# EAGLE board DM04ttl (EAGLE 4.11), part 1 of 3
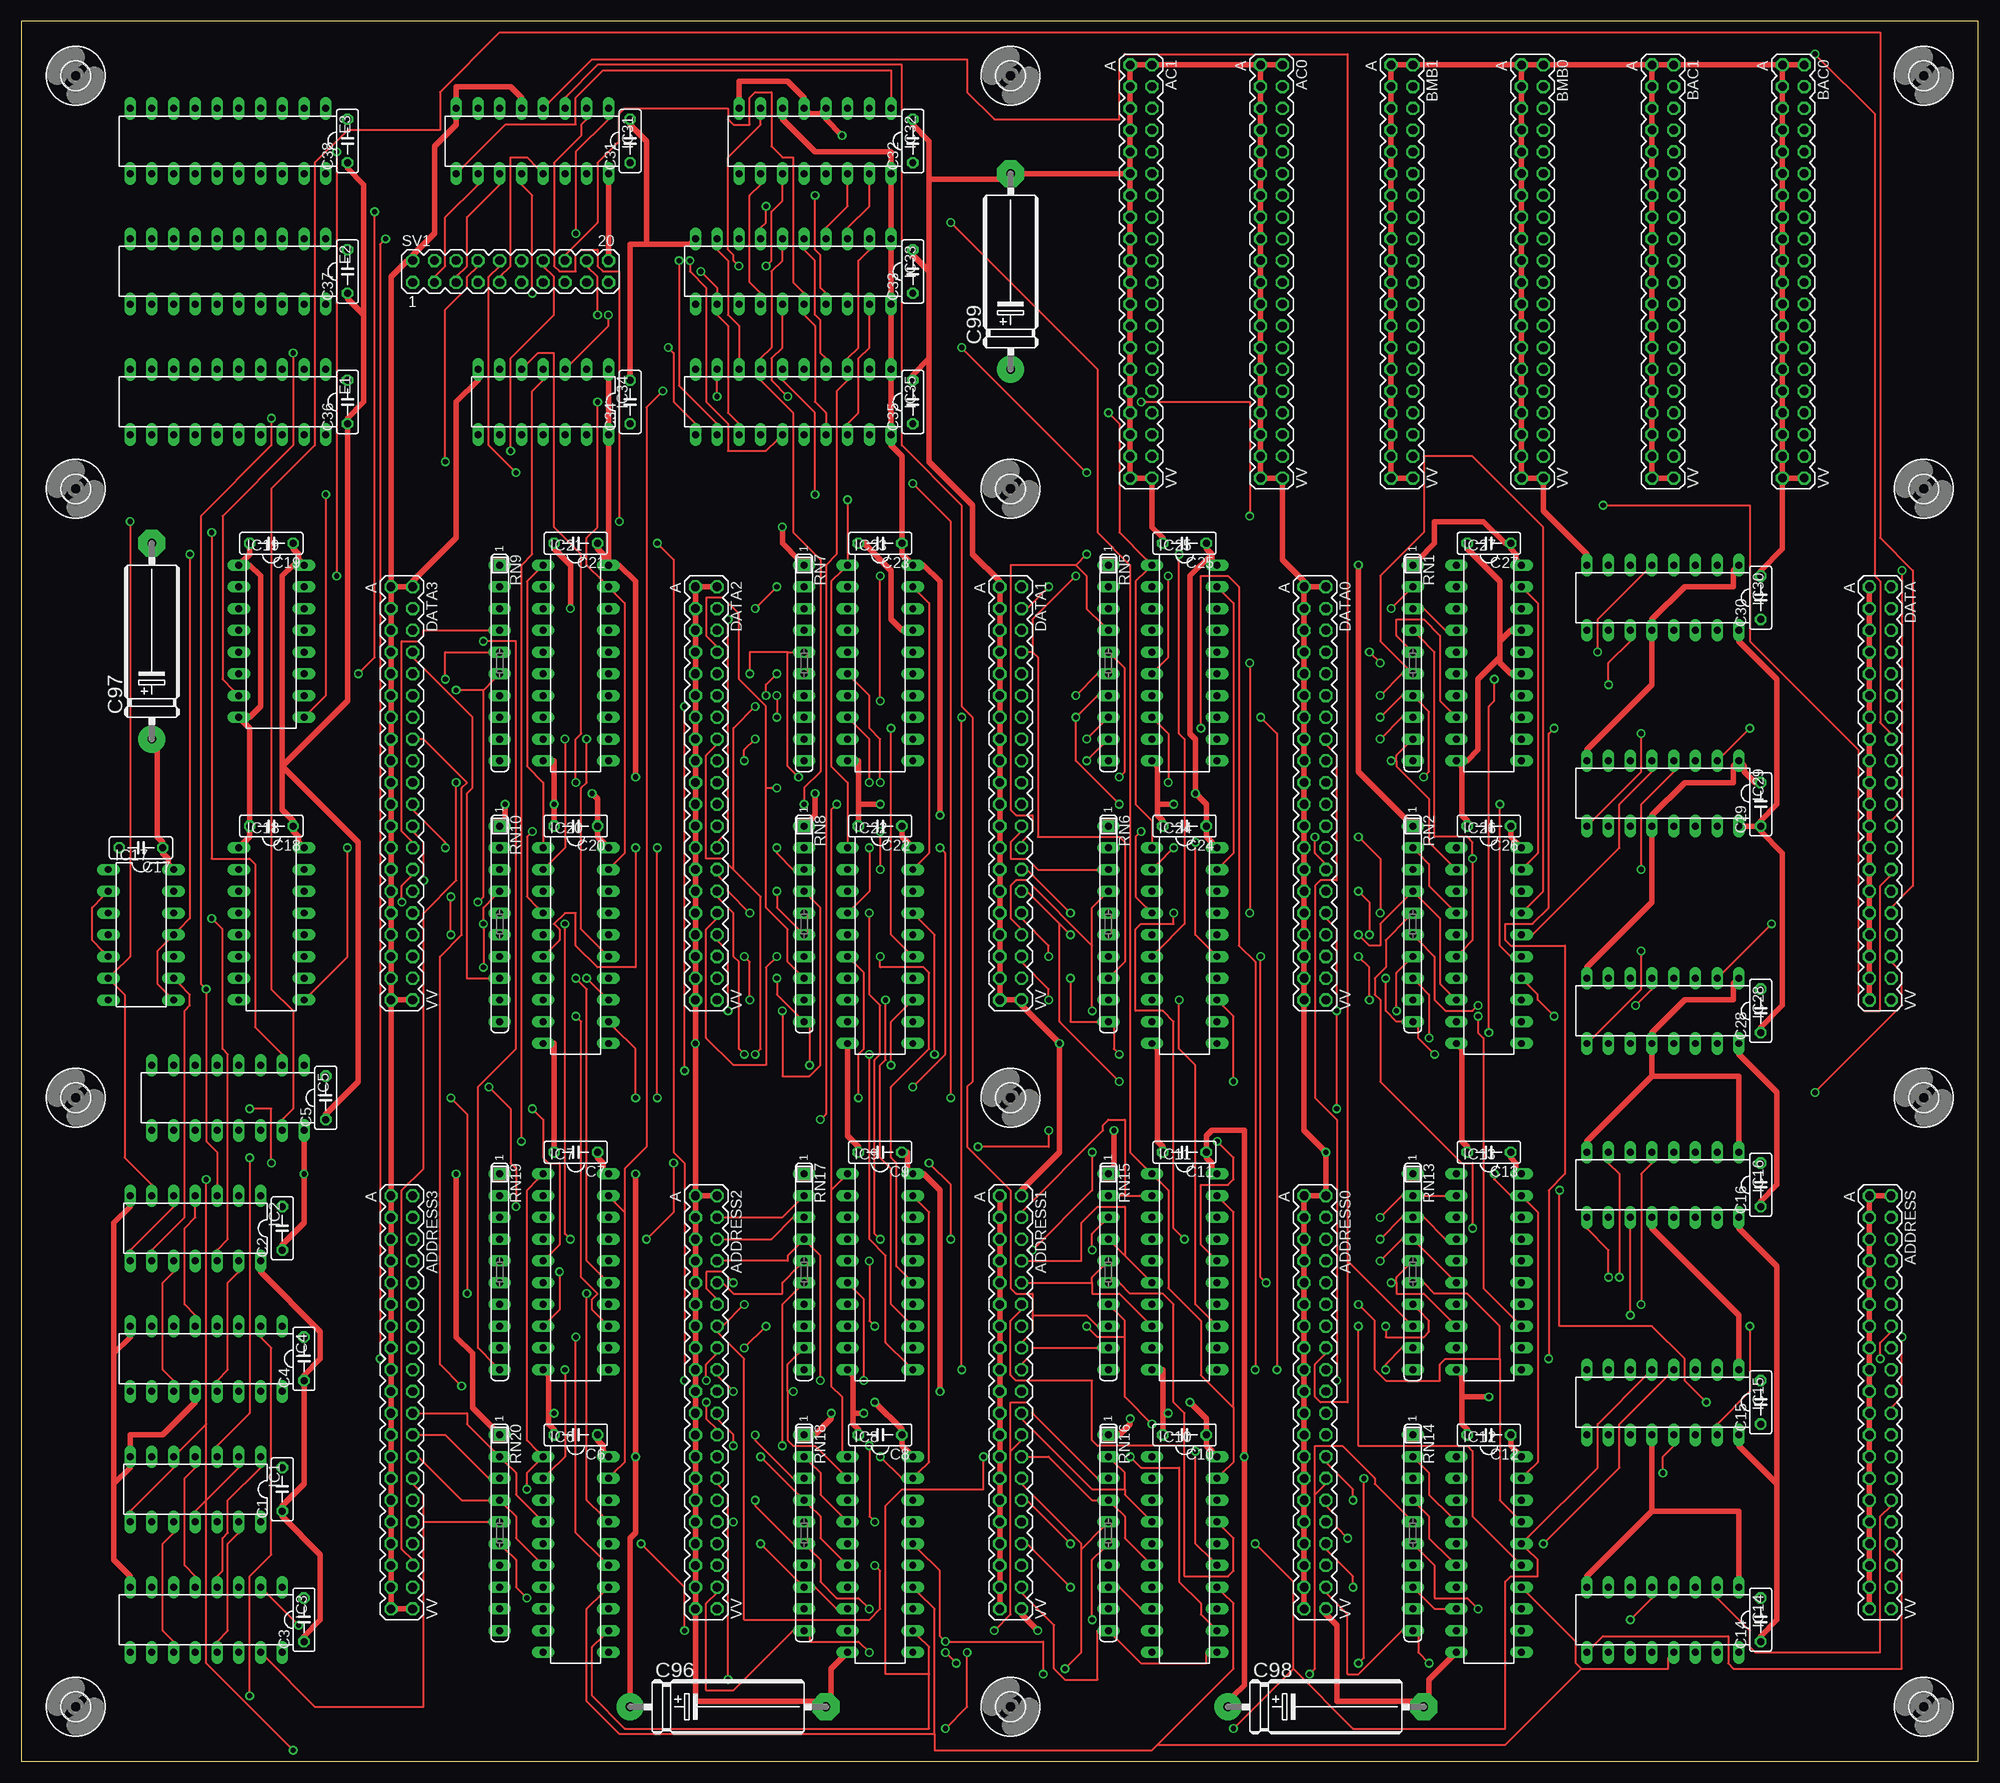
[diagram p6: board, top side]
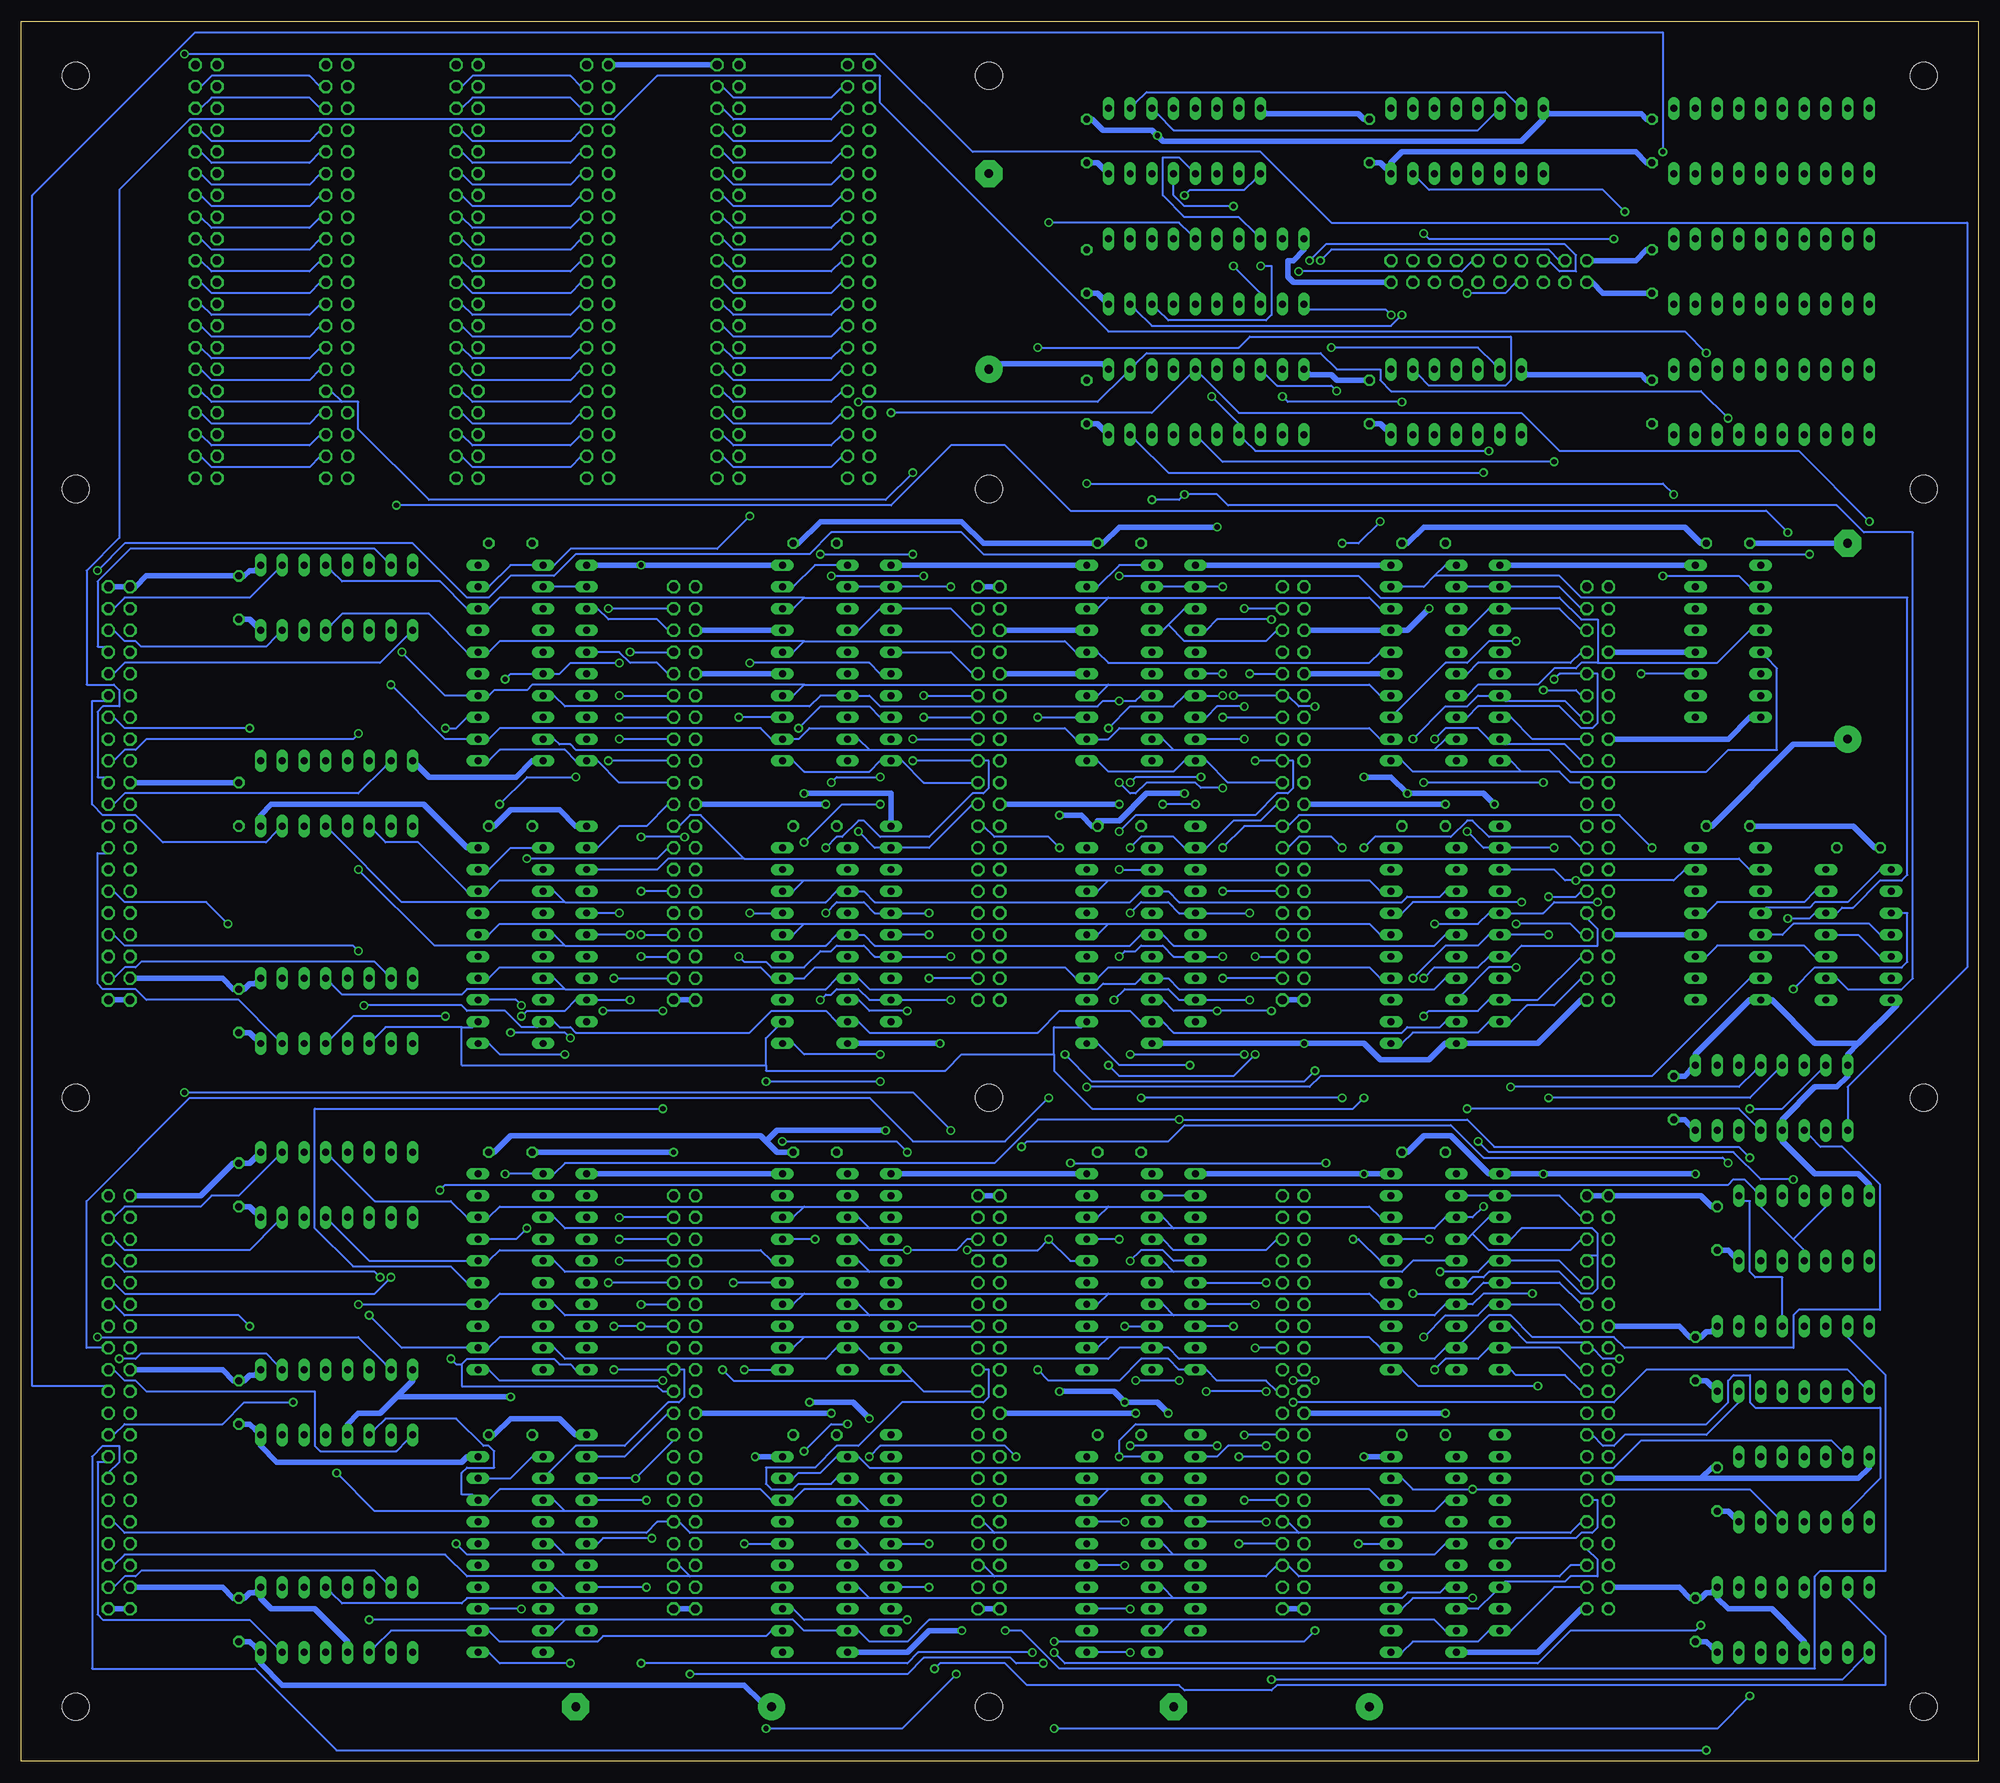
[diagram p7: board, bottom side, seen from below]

Size 228.6 x 203.2 mm. Coordinates in mm from the lower left corner, seen from the top.
Outline: 0,0 228.6,0 228.6,203.2 0,203.2 0,0
Copper layers (1*16): Top 0.035mm / dielectric 1.5mm / Bottom 0.035mm
Design rules "10mils": minimum track width 10mil, minimum drill 24mil, track to track 10mil, track to pad 10mil, pad to pad 10mil, via to via 10mil, smd to smd 10mil, copper to edge 25mil, drill to drill 10mil, minimum pad ring 10mil, minimum via ring 8mil, stop-mask expansion 0mil, vias tented up to drill 0mil, thermal gap 10mil
Net classes: 1 Supply: width 0.635 mm, drill 0.381 mm

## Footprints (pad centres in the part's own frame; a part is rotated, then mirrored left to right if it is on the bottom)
DEC40PINV = drill 1.016 octagon: A -24.13,-1.27; AA 3.81,-1.27; B -24.13,1.27; BB 3.81,1.27; C -21.59,-1.27; CC 6.35,-1.27; D -21.59,1.27; DD 6.35,1.27; E -19.05,-1.27; EE 8.89,-1.27; F -19.05,1.27; FF 8.89,1.27; H -16.51,-1.27; HH 11.43,-1.27; J -16.51,1.27; JJ 11.43,1.27; K -13.97,-1.27; KK 13.97,-1.27; L -13.97,1.27; LL 13.97,1.27; M -11.43,-1.27; MM 16.51,-1.27; N -11.43,1.27; NN 16.51,1.27; P -8.89,-1.27; PP 19.05,-1.27; R -8.89,1.27; RR 19.05,1.27; S -6.35,-1.27; SS 21.59,-1.27; T -6.35,1.27; TT 21.59,1.27; U -3.81,-1.27; UU 24.13,-1.27; V -3.81,1.27; VV 24.13,1.27; W -1.27,-1.27; X -1.27,1.27; Y 1.27,-1.27; Z 1.27,1.27
C050-025X075 = drill 0.813 octagon: 1 -2.54,0; 2 2.54,0
E22-6 = drill 1.016 pad 3.15 round: + -11.43,0 | drill 1.016 pad 3.15 octagon: - 11.43,0
DIL20 = drill 0.813 long: 1 -11.43,-3.81; 2 -8.89,-3.81; 3 -6.35,-3.81; 4 -3.81,-3.81; 5 -1.27,-3.81; 6 1.27,-3.81; 7 3.81,-3.81; 8 6.35,-3.81; 9 8.89,-3.81; 10 11.43,-3.81; 11 11.43,3.81; 12 8.89,3.81; 13 6.35,3.81; 14 3.81,3.81; 15 1.27,3.81; 16 -1.27,3.81; 17 -3.81,3.81; 18 -6.35,3.81; 19 -8.89,3.81; 20 -11.43,3.81
DIL14 = drill 0.813 long: 1 -7.62,-3.81; 2 -5.08,-3.81; 3 -2.54,-3.81; 4 0,-3.81; 5 2.54,-3.81; 6 5.08,-3.81; 7 7.62,-3.81; 8 7.62,3.81; 9 5.08,3.81; 10 2.54,3.81; 11 0,3.81; 12 -2.54,3.81; 13 -5.08,3.81; 14 -7.62,3.81
DIL16 = drill 0.813 long: 1 -8.89,-3.81; 2 -6.35,-3.81; 3 -3.81,-3.81; 4 -1.27,-3.81; 5 1.27,-3.81; 6 3.81,-3.81; 7 6.35,-3.81; 8 8.89,-3.81; 9 8.89,3.81; 10 6.35,3.81; 11 3.81,3.81; 12 1.27,3.81; 13 -1.27,3.81; 14 -3.81,3.81; 15 -6.35,3.81; 16 -8.89,3.81
SIL10 = drill 0.813 long: 1 -11.43,0; 2 -8.89,0; 3 -6.35,0; 4 -3.81,0; 5 -1.27,0; 6 1.27,0; 7 3.81,0; 8 6.35,0; 9 8.89,0; 10 11.43,0
MA10-2 = drill 1.016 octagon: 1 -11.43,-1.27; 2 -11.43,1.27; 3 -8.89,-1.27; 4 -8.89,1.27; 5 -6.35,-1.27; 6 -6.35,1.27; 7 -3.81,-1.27; 8 -3.81,1.27; 9 -1.27,-1.27; 10 -1.27,1.27; 11 1.27,-1.27; 12 1.27,1.27; 13 3.81,-1.27; 14 3.81,1.27; 15 6.35,-1.27; 16 6.35,1.27; 17 8.89,-1.27; 18 8.89,1.27; 19 11.43,-1.27; 20 11.43,1.27
3,2 = hole 3.2: 0,0

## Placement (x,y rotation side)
AC0  BC08J  [DEC40PINV]  146.05,173.99 270 top
AC1  BC08J  [DEC40PINV]  130.81,173.99 270 top
ADDRESS  BC08J  [DEC40PINV]  217.17,41.91 270 top
ADDRESS0  BC08J  [DEC40PINV]  151.13,41.91 270 top
ADDRESS1  BC08J  [DEC40PINV]  115.57,41.91 270 top
ADDRESS2  BC08J  [DEC40PINV]  80.01,41.91 270 top
ADDRESS3  BC08J  [DEC40PINV]  44.45,41.91 270 top
BAC0  BC08J  [DEC40PINV]  207.01,173.99 270 top
BAC1  BC08J  [DEC40PINV]  191.77,173.99 270 top
BMB0  BC08J  [DEC40PINV]  176.53,173.99 270 top
BMB1  BC08J  [DEC40PINV]  161.29,173.99 270 top
C1  .1uf  [C050-025X075]  30.48,31.75 90 top
C2  .1uf  [C050-025X075]  30.48,62.23 90 top
C3  .1uf  [C050-025X075]  33.02,16.51 90 top
C4  .1uf  [C050-025X075]  33.02,46.99 90 top
C5  .1uf  [C050-025X075]  35.56,77.47 90 top
C6  .1uf  [C050-025X075]  64.77,38.1 180 top
C7  .1uf  [C050-025X075]  64.77,71.12 180 top
C8  .1uf  [C050-025X075]  100.33,38.1 180 top
C9  .1uf  [C050-025X075]  100.33,71.12 180 top
C10  .1uf  [C050-025X075]  135.89,38.1 180 top
C11  .1uf  [C050-025X075]  135.89,71.12 180 top
C12  .1uf  [C050-025X075]  171.45,38.1 180 top
C13  .1uf  [C050-025X075]  171.45,71.12 180 top
C14  .1uf  [C050-025X075]  203.2,16.51 90 top
C15  .1uf  [C050-025X075]  203.2,41.91 90 top
C16  .1uf  [C050-025X075]  203.2,67.31 90 top
C17  .1uf  [C050-025X075]  13.97,106.68 180 top
C18  .1uf  [C050-025X075]  29.21,109.22 180 top
C19  .1uf  [C050-025X075]  29.21,142.24 180 top
C20  .1uf  [C050-025X075]  64.77,109.22 180 top
C21  .1uf  [C050-025X075]  64.77,142.24 180 top
C22  .1uf  [C050-025X075]  100.33,109.22 180 top
C23  .1uf  [C050-025X075]  100.33,142.24 180 top
C24  .1uf  [C050-025X075]  135.89,109.22 180 top
C25  .1uf  [C050-025X075]  135.89,142.24 180 top
C26  .1uf  [C050-025X075]  171.45,109.22 180 top
C27  .1uf  [C050-025X075]  171.45,142.24 180 top
C28  .1uf  [C050-025X075]  203.2,87.63 90 top
C29  .1uf  [C050-025X075]  203.2,111.76 90 top
C30  .1uf  [C050-025X075]  203.2,135.89 90 top
C31  .1uf  [C050-025X075]  71.12,189.23 90 top
C32  .1uf  [C050-025X075]  104.14,189.23 90 top
C33  .1uf  [C050-025X075]  104.14,173.99 90 top
C34  .1uf  [C050-025X075]  71.12,158.75 90 top
C35  .1uf  [C050-025X075]  104.14,158.75 90 top
C36  .1uf  [C050-025X075]  38.1,158.75 90 top
C37  .1uf  [C050-025X075]  38.1,173.99 90 top
C38  .1uf  [C050-025X075]  38.1,189.23 90 top
C96  100uf  [E22-6]  82.55,6.35 0 top
C97  100uf  [E22-6]  15.24,130.81 90 top
C98  100uf  [E22-6]  152.4,6.35 0 top
C99  100uf  [E22-6]  115.57,173.99 90 top
DATA  BC08J  [DEC40PINV]  217.17,113.03 270 top
DATA0  BC08J  [DEC40PINV]  151.13,113.03 270 top
DATA1  BC08J  [DEC40PINV]  115.57,113.03 270 top
DATA2  BC08J  [DEC40PINV]  80.01,113.03 270 top
DATA3  BC08J  [DEC40PINV]  44.45,113.03 270 top
E1  [DIL20]  24.13,158.75 180 top
E2  [DIL20]  24.13,173.99 180 top
E3  [DIL20]  24.13,189.23 180 top
IC1  74S02N  [DIL14]  20.32,31.75 180 top
IC2  74S02N  [DIL14]  20.32,62.23 180 top
IC3  AM26S10  [DIL16]  21.59,16.51 180 top
IC4  AM26S10  [DIL16]  21.59,46.99 180 top
IC5  AM26S10  [DIL16]  24.13,77.47 180 top
IC6  74S240N  [DIL20]  64.77,24.13 270 top
IC7  74S240N  [DIL20]  64.77,57.15 270 top
IC8  74S240N  [DIL20]  100.33,24.13 270 top
IC9  74S240N  [DIL20]  100.33,57.15 270 top
IC10  74S240N  [DIL20]  135.89,24.13 270 top
IC11  74S240N  [DIL20]  135.89,57.15 270 top
IC12  74S240N  [DIL20]  171.45,24.13 270 top
IC13  74S240N  [DIL20]  171.45,57.15 270 top
IC14  AM26S10  [DIL16]  191.77,16.51 180 top
IC15  AM26S10  [DIL16]  191.77,41.91 180 top
IC16  AM26S10  [DIL16]  191.77,67.31 180 top
IC17  74S02N  [DIL14]  13.97,96.52 270 top
IC18  AM26S10  [DIL16]  29.21,97.79 270 top
IC19  AM26S10  [DIL16]  29.21,130.81 270 top
IC20  74S240N  [DIL20]  64.77,95.25 270 top
IC21  74S240N  [DIL20]  64.77,128.27 270 top
IC22  74S240N  [DIL20]  100.33,95.25 270 top
IC23  74S240N  [DIL20]  100.33,128.27 270 top
IC24  74S240N  [DIL20]  135.89,95.25 270 top
IC25  74S240N  [DIL20]  135.89,128.27 270 top
IC26  74S240N  [DIL20]  171.45,95.25 270 top
IC27  74S240N  [DIL20]  171.45,128.27 270 top
IC28  AM26S10  [DIL16]  191.77,87.63 180 top
IC29  AM26S10  [DIL16]  191.77,113.03 180 top
IC30  AM26S10  [DIL16]  191.77,135.89 180 top
IC31  74LS148N  [DIL16]  59.69,189.23 180 top
IC32  74S138N  [DIL16]  92.71,189.23 180 top
IC33  74LS273N  [DIL20]  90.17,173.99 180 top
IC34  74S86N  [DIL14]  60.96,158.75 180 top
IC35  74LS273N  [DIL20]  90.17,158.75 180 top
RN1  [SIL10]  162.56,128.27 270 top
RN2  [SIL10]  162.56,97.79 270 top
RN5  [SIL10]  127,128.27 270 top
RN6  [SIL10]  127,97.79 270 top
RN7  [SIL10]  91.44,128.27 270 top
RN8  [SIL10]  91.44,97.79 270 top
RN9  [SIL10]  55.88,128.27 270 top
RN10  [SIL10]  55.88,97.79 270 top
RN13  [SIL10]  162.56,57.15 270 top
RN14  [SIL10]  162.56,26.67 270 top
RN15  [SIL10]  127,57.15 270 top
RN16  [SIL10]  127,26.67 270 top
RN17  [SIL10]  91.44,57.15 270 top
RN18  [SIL10]  91.44,26.67 270 top
RN19  [SIL10]  55.88,57.15 270 top
RN20  [SIL10]  55.88,26.67 270 top
SV1  [MA10-2]  57.15,173.99 0 top
U$1  [3,2]  222.25,6.35 270 top
U$2  [3,2]  6.35,196.85 270 top
U$3  [3,2]  222.25,196.85 270 top
U$4  [3,2]  6.35,6.35 270 top
U$5  [3,2]  115.57,196.85 270 top
U$6  [3,2]  115.57,77.47 270 top
U$7  [3,2]  222.25,148.59 270 top
U$8  [3,2]  222.25,77.47 270 top
U$9  [3,2]  6.35,77.47 270 top
U$10  [3,2]  6.35,148.59 270 top
U$11  [3,2]  115.57,6.35 270 top
U$12  [3,2]  115.57,148.59 270 top

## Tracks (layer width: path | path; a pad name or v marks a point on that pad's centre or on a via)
1-CA_INH
  Bottom 0.254: 63.5,118.11 62.23,119.38 IC21.9 | 93.98,118.11 63.5,118.11 | 93.98,118.11 95.25,119.38 IC23.9 | 63.5,118.11 50.16,118.11 47.62,115.57 31.75,115.57 29.21,118.11 23.5,118.11 23.5,127.64 24.77,128.91 IC19.5 | 129.54,118.11 130.81,119.38 IC25.9 | 129.54,118.11 93.98,118.11 | 129.54,118.11 163.83,118.11 164.47,118.75 165.74,118.75 166.37,119.38 IC27.9
1-CA_INH0\
  Bottom 0.254: DATA0.X 153.03,114.3 158.75,114.3 161.29,116.84 RN1.10 163.83,116.84 165.1,118.11 172.72,118.11 173.99,116.84 IC27.11
1-CA_INH1\
  Bottom 0.254: DATA1.X 117.47,114.3 123.19,114.3 125.73,116.84 RN5.10 128.27,116.84 129.54,115.57 137.16,115.57 138.43,116.84 IC25.11
1-CA_INH2\
  Bottom 0.254: DATA2.X 81.92,114.3 87.63,114.3 90.17,116.84 RN7.10 92.71,116.84 93.98,115.57 101.6,115.57 102.87,116.84 IC23.11
1-CA_INH3\
  Bottom 0.254: 53.34,115.57 54.61,116.84 RN9.10 | 53.34,115.57 48.9,115.57 47.62,114.3 46.35,114.3 DATA3.X | 53.34,115.57 66.04,115.57 67.31,116.84 IC21.11
1-CA_INH\  (via drill 0.61)
  Top 0.254: v31.75,164.47 31.75,153.67 23.5,145.41 23.5,126.36 24.77,125.09 IC19.7
  Bottom 0.254: v31.75,164.47 34.29,167 101.6,167 128.27,193.68 128.27,196.85 154.31,196.85 159.38,191.77 208.91,191.77 217.17,183.51 217.17,142.88 220.98,139.06 220.98,125.73 217.81,125.73 217.17,125.09 217.17,123.19 219.07,123.19 219.71,122.56 219.71,114.94 218.44,114.94 DATA.X
3CYCLE
  Bottom 0.254: IC13.9 166.37,48.26 165.1,46.99 134.62,46.99 133.35,48.26 IC11.9 130.81,48.26 129.54,46.99 101.6,46.99 100.33,48.26 97.79,48.26 IC9.9 95.25,48.26 94.61,48.26 93.34,46.99 63.5,46.99 62.23,48.26 IC7.9 60.33,48.9 57.15,52.07 54.61,52.07 52.07,49.53 42.55,49.53 41.27,48.26 21.59,48.26 21.59,52.07 20.95,52.7 11.43,52.7 11.43,67.31 15.88,71.75 18.41,71.75 19.68,73.03 IC5.11
3CYCLE0\  (via drill 0.61)
  Top 0.254: v158.75,119.38 161.29,121.92 RN1.8 | v153.67,44.45 153.67,74.93 151.13,77.47 151.13,102.23 151.76,102.87 153.67,102.87 153.67,117.47 152.4,118.75 DATA0.T
  Bottom 0.254: v158.75,119.38 153.03,119.38 DATA0.T | v153.67,44.45 172.72,44.45 173.99,45.72 IC13.11
3CYCLE1\  (via drill 0.61)
  Top 0.254: v144.15,45.72 144.15,93.34 142.24,95.25 142.24,137.16 140.97,138.43 137.79,138.43 v137.79,120.65 | v124.46,119.38 126.36,121.28 RN5.8
  Bottom 0.254: v144.15,45.72 140.97,45.72 IC11.11 | v137.79,120.65 135.25,123.19 129.54,123.19 128.27,121.92 RN5.8 | v124.46,119.38 117.47,119.38 DATA1.T
3CYCLE2\  (via drill 0.61)
  Top 0.254: v99.06,82.55 99.06,60.96 100.97,59.05 100.97,48.9 103.5,46.35 IC9.11 | v85.72,82.55 86.36,83.19 86.36,100.97 83.19,104.14 | 83.19,104.14 81.92,105.41 80.01,105.41 80.01,117.47 81.28,118.75 DATA2.T | v85.72,123.19 83.19,120.65 83.19,104.14
  Bottom 0.254: v99.06,82.55 v85.72,82.55 | v85.72,123.19 88.9,123.19 90.17,121.92 RN7.8
3CYCLE3\  (via drill 0.61)
  Top 0.254: v51.44,43.81 48.9,46.35 48.9,93.98 51.44,96.52 51.44,113.67 52.07,114.3 46.99,119.38 46.35,119.38 DATA3.T
  Bottom 0.254: v51.44,43.81 65.41,43.81 67.31,45.72 IC7.11 | RN9.8 54.61,121.92 52.07,119.38 46.35,119.38 DATA3.T
3CYCLE\  (via drill 0.61)
  Top 0.254: v209.55,199.39 216.53,192.41 216.53,138.43 217.17,137.79 217.17,121.28 218.44,120.02 DATA.T
  Bottom 0.254: v209.55,199.39 128.91,199.39 117.47,187.96 83.82,187.96 75.56,179.71 1.27,179.71 1.27,92.71 15.24,78.74 15.24,74.93 IC5.9
A_EN0\  (via drill 0.61)
  Top 0.254: IC12.19 175.9,33.66 177.16,34.92 177.16,64.14 175.9,65.41 IC13.19 173.99,66.04 172.09,67.94 v172.09,68.58 | IC33.2 99.06,176.53 97.79,175.26 97.79,165.1 96.52,163.83 IC35.3 96.52,161.29 95.25,160.02 95.25,140.97 93.98,139.7 93.98,75.56 v93.34,74.93 | v26.67,70.48 26.67,40.64 22.86,36.83 IC1.3
  Bottom 0.254: IC12.1 168.91,35.56 171.45,33.02 173.99,33.02 IC12.19 | v26.67,70.48 27.94,71.75 56.52,71.75 59.69,74.93 v93.34,74.93 109.86,74.93 114.94,69.85 165.1,69.85 166.37,68.58 IC13.1 168.91,68.58 v172.09,68.58
A_EN1\  (via drill 0.61)
  Top 0.254: IC35.4 93.98,163.83 93.34,164.47 93.34,168.28 92.71,168.91 92.71,175.26 91.44,176.53 IC33.5 | 141.6,41.27 141.6,34.92 140.34,33.66 IC10.19 | 141.6,41.27 141.6,64.14 140.34,65.41 IC11.19 | 141.6,41.27 137.79,45.09 137.79,51.44 133.99,55.24 133.99,66.67 132.72,67.94 IC11.1 131.44,69.22 129.54,71.12 129.54,139.7 125.73,143.51 125.73,162.56 v108.58,179.71
  Bottom 0.254: IC1.6 15.88,36.2 17.14,37.47 39.37,37.47 42.55,34.29 129.54,34.29 130.81,35.56 IC10.1 133.35,35.56 135.25,33.66 137.79,33.66 138.43,33.02 IC10.19 | v108.58,179.71 93.34,179.71 92.08,178.44 IC33.5
A_EN2\  (via drill 0.61)
  Top 0.254: IC9.19 104.78,65.41 106.05,64.14 106.05,34.92 104.78,33.66 IC8.19 102.87,33.02 v100.33,35.56 | IC33.6 88.9,176.53 88.9,175.26 87.63,173.99 87.63,165.1 86.36,163.83 IC35.7 86.36,161.29 90.17,157.48 90.17,143.51 93.34,140.34 93.34,115.57 91.44,113.67 v91.44,111.76 | 94.61,66.67 95.89,67.94 IC9.1 | 94.61,66.67 94.61,43.81 95.89,42.55 95.89,36.2 IC8.1 | v95.25,111.76 94.61,111.12 94.61,66.67
  Bottom 0.254: IC1.9 15.24,29.21 11.43,33.02 11.43,41.27 26.04,41.27 26.67,41.91 26.67,45.09 28.57,45.09 29.21,44.45 29.21,41.91 31.75,39.37 98.42,39.37 100.33,37.47 v100.33,35.56 97.79,35.56 IC8.1 | v91.44,111.76 v95.25,111.76
A_EN3\  (via drill 0.61)
  Top 0.254: IC7.1 60.33,67.94 59.05,66.67 59.05,37.47 60.33,36.2 IC6.1 60.33,34.92 59.05,33.66 v59.05,31.75 | IC33.9 81.28,176.53 82.55,175.26 82.55,168.91 83.82,167.64 83.82,163.83 IC35.8 | 70.48,64.14 69.22,65.41 IC7.19 | 70.48,64.14 70.48,34.92 69.22,33.66 IC6.19 | v74.93,160.02 73.03,158.12 73.03,71.75 70.48,69.22 70.48,64.14
  Bottom 0.254: IC1.12 23.5,28.57 26.67,31.75 v59.05,31.75 66.04,31.75 67.31,33.02 IC6.19 | v74.93,160.02 75.56,160.66 81.92,160.66 83.19,161.93 IC35.8
A_EN4\  (via drill 0.61)
  Top 0.254: IC35.13 83.82,156.21 82.55,157.48 82.55,167.64 81.28,168.91 IC33.12 81.28,171.45 81.28,172.09 v79.38,173.99
  Bottom 0.254: v79.38,173.99 60.33,173.99 59.05,175.26 SV1.12
A_EN5\  (via drill 0.61)
  Top 0.254: v89.53,159.38 87.63,161.29 87.63,163.83 88.9,165.1 88.9,168.91 IC33.15 | v57.15,153.03 57.15,163.83 62.23,168.91 62.23,173.35 60.96,174.62 SV1.14
  Bottom 0.254: v89.53,159.38 86.36,156.21 IC35.14 85.72,154.31 84.45,153.03 v57.15,153.03
A_EN6\
  Top 0.254: IC35.17 93.98,156.21 93.98,157.48 92.71,158.75 92.71,167.64 91.44,168.91 IC33.16 91.44,171.45 90.17,172.72 90.17,187.32 88.9,187.32 87.63,188.59 87.63,194.94 85.72,194.94 85.09,194.31 85.09,191.13 83.19,191.13 82.55,191.77 82.55,193.04 70.48,193.04 69.85,192.41 69.85,189.23 67.31,186.69 67.31,179.71 63.5,175.9 SV1.16
A_EN7\  (via drill 0.61)
  Top 0.254: IC35.18 96.52,156.21 97.79,157.48 97.79,163.83 99.06,165.1 99.06,168.91 IC33.19 | v67.31,168.91 67.31,173.35 66.04,174.62 SV1.18
  Bottom 0.254: v67.31,168.91 68.58,167.64 96.52,167.64 98.42,169.54 IC33.19
AC_CLEAR\
  Bottom 0.254: AC1.BB 132.72,170.18 133.99,168.91 145.41,168.91 146.69,170.18 AC0.BB
ADD_ACC0\  (via drill 0.61)
  Top 0.254: v32.38,15.88 28.57,19.68 IC3.2 | v107.95,12.7 v109.22,11.43 | v150.5,10.16 151.13,10.79 151.13,31.11 | 151.13,31.11 152.4,32.38 ADDRESS0.FF | 151.13,31.11 151.13,36.83 154.31,36.83 158.12,33.02 158.12,32.38 161.93,28.57 RN14.5
  Bottom 0.254: v32.38,15.88 33.02,15.24 47.62,15.24 51.44,11.43 106.68,11.43 v107.95,12.7 | v109.22,11.43 112.39,11.43 113.03,12.06 123.19,12.06 125.09,10.16 v150.5,10.16
ADD_ACC1\  (via drill 0.61)
  Top 0.254: v121.92,10.79 123.83,12.7 123.83,24.77 | 123.83,24.77 126.36,27.3 RN16.5 | 123.83,24.77 123.83,25.4 116.84,32.38 ADDRESS1.FF
  Bottom 0.254: v121.92,10.79 121.28,11.43 113.67,11.43 111.12,8.89 93.34,8.89 92.71,8.26 82.55,8.26 81.92,8.89 10.79,8.89 10.79,14.61 15.24,19.05 IC3.7
ADD_ACC2\  (via drill 0.61)
  Top 0.254: 82.55,27.94 82.55,31.11 81.28,32.38 ADDRESS2.FF | v82.55,9.53 82.55,27.94 | 82.55,27.94 v83.19,27.94
  Bottom 0.254: v82.55,9.53 15.88,9.53 13.34,12.06 IC3.9 | v83.19,27.94 90.17,27.94 RN18.5
ADD_ACC3\
  Top 0.254: 46.99,27.94 46.99,31.11 45.72,32.38 ADDRESS3.FF | 46.99,27.94 46.99,6.35 34.29,6.35 28.57,12.06 IC3.15 | 46.99,27.94 54.61,27.94 RN20.5
ADD_ACC\  (via drill 0.61)
  Top 0.254: IC1.8 12.7,29.21 17.78,34.29 IC1.5 18.41,36.2 21.59,39.37 | 21.59,30.48 25.4,34.29 IC1.2 | 21.59,30.48 20.32,29.21 IC1.11 | v58.42,72.39 58.42,139.7 59.69,140.97 59.69,160.02 60.96,161.29 IC34.4 | 21.59,30.48 21.59,39.37 | 21.59,39.37 v21.59,67.94 | v31.75,1.27 21.59,11.43 21.59,30.48
  Bottom 0.254: v58.42,72.39 57.15,71.12 28.57,71.12 25.4,67.94 v21.59,67.94 | v31.75,1.27 191.77,1.27 201.29,10.79 220.34,10.79 220.34,35.56 219.07,36.83 217.17,36.83 217.17,34.92 218.44,33.66 ADDRESS.FF
B_EN0\  (via drill 0.61)
  Top 0.254: IC2.3 22.86,67.31 22.86,71.12 21.59,72.39 v21.59,90.17 20.95,90.81 20.95,145.41 29.21,153.67 v29.21,156.84 | v130.81,158.75 143.51,158.75 v143.51,145.41 | IC26.19 175.9,104.78 177.16,106.05 177.16,135.25 175.9,136.53 IC27.19
  Bottom 0.254: v21.59,90.17 19.05,92.71 8.89,92.71 8.26,93.34 8.26,99.06 8.89,99.06 IC17.3 | IC26.19 173.99,104.14 171.45,106.68 168.91,106.68 IC26.1 | v130.81,158.75 102.87,158.75 99.69,161.93 IC35.2 98.42,163.19 97.16,164.47 76.83,164.47 74.93,162.56 69.85,162.56 69.85,161.29 68.58,160.02 32.38,160.02 v29.21,156.84 | v143.51,145.41 147.32,141.6 164.47,141.6 166.37,139.7 IC27.1 168.91,139.7 171.45,139.7 173.99,137.16 IC27.19
B_EN1\  (via drill 0.61)
  Top 0.254: IC24.19 140.34,104.78 141.6,106.05 141.6,135.25 140.34,136.53 IC25.19 | IC2.6 15.24,67.31 12.06,70.48 12.06,89.53 10.79,90.81 IC17.6 10.79,92.08 12.7,93.98 v12.7,144.78 | IC24.1 132.08,107.31 132.08,109.86 130.18,111.76 130.18,137.79 131.44,139.06 IC25.1 131.44,140.34 128.27,143.51 128.27,156.21 v127,157.48
  Bottom 0.254: v127,157.48 96.52,157.48 92.08,161.93 IC35.5 90.81,161.93 86.36,157.48 53.34,157.48 48.9,153.03 20.95,153.03 v12.7,144.78 | IC25.19 138.43,137.16 135.89,139.7 133.35,139.7 IC25.1
B_EN2\  (via drill 0.61)
  Top 0.254: IC2.9 15.24,59.69 19.05,63.5 19.05,87.63 19.68,88.27 19.68,89.53 18.41,90.81 IC17.9 | IC22.19 104.78,104.78 106.05,106.05 106.05,135.25 104.78,136.53 IC23.19 | IC22.1 96.52,107.31 96.52,114.3 94.61,116.2 94.61,137.79 95.89,139.06 IC23.1 96.52,140.34 v96.52,147.32 | v92.71,147.96 92.71,157.48 88.9,161.29 IC35.6
  Bottom 0.254: v96.52,147.32 93.34,147.32 v92.71,147.96 88.9,147.96 87.63,146.69 16.51,146.69 13.34,143.51 7.62,143.51 7.62,91.44 8.89,90.17 15.24,90.17 16.51,91.44 IC17.9 | IC23.19 102.87,137.16 100.33,139.7 97.79,139.7 IC23.1
B_EN3\  (via drill 0.61)
  Top 0.254: v22.23,98.42 23.5,97.16 23.5,83.19 24.13,82.55 24.13,60.96 22.86,59.69 IC2.12 | IC20.1 60.96,107.31 60.96,114.3 59.05,116.2 59.05,137.79 60.33,139.06 IC21.1 | IC20.19 69.22,104.78 70.48,106.05 70.48,135.25 69.22,136.53 IC21.19 67.94,137.79 66.04,139.7 66.04,142.88 67.31,144.15 v67.31,158.75 | v81.28,159.38 81.28,161.29 IC35.9
  Bottom 0.254: v22.23,98.42 19.68,98.42 19.05,99.06 IC17.12 16.51,99.06 15.88,99.69 14.61,99.69 11.43,102.87 8.89,102.87 8.26,103.5 8.26,135.89 46.35,135.89 48.9,138.43 63.5,138.43 | v81.28,159.38 80.64,158.75 v67.31,158.75 | 63.5,138.43 64.77,137.16 67.31,137.16 IC21.19 | 63.5,138.43 62.23,139.7 IC21.1
B_EN4\  (via drill 0.61)
  Top 0.254: v76.83,175.26 76.83,160.66 81.28,156.21 IC35.12
  Bottom 0.254: v76.83,175.26 75.56,176.53 50.16,176.53 48.9,175.26 SV1.4
B_EN5\  (via drill 0.61)
  Top 0.254: v78.11,175.26 78.11,173.99 80.01,172.09 80.01,158.75 82.55,156.21 82.55,153.03 87,153.03 88.27,154.31 IC35.15
  Bottom 0.254: v78.11,175.26 76.2,177.16 48.26,177.16 46.99,175.9 46.99,173.99 48.9,173.99 50.16,175.26 SV1.6
B_EN6\  (via drill 0.61)
  Top 0.254: v49.53,151.76 49.53,169.54 52.07,172.09 52.07,173.35 53.34,174.62 SV1.8
  Bottom 0.254: v49.53,151.76 88.27,151.76 90.81,154.31 IC35.16
B_EN7\  (via drill 0.61)
  Top 0.254: v57.78,150.5 54.61,153.67 54.61,173.35 55.88,174.62 SV1.10
  Bottom 0.254: v57.78,150.5 94.61,150.5 98.42,154.31 IC35.19
BAC0
  Bottom 0.254: BAC1.F 193.68,193.04 194.94,194.31 206.38,194.31 207.65,193.04 BAC0.F
BAC1
  Bottom 0.254: BAC1.L 193.68,187.96 194.94,186.69 206.38,186.69 207.65,187.96 BAC0.L
BAC2
  Bottom 0.254: BAC1.R 193.68,182.88 194.94,181.61 206.38,181.61 207.65,182.88 BAC0.R
BAC3
  Bottom 0.254: BAC1.V 193.68,177.8 194.94,176.53 206.38,176.53 207.65,177.8 BAC0.V
BAC4
  Bottom 0.254: BAC1.Z 193.68,172.72 194.94,171.45 206.38,171.45 207.65,172.72 BAC0.Z
BAC5
  Bottom 0.254: BAC1.DD 193.68,167.64 194.94,166.37 206.38,166.37 207.65,167.64 BAC0.DD
BAC6
  Bottom 0.254: BAC1.JJ 193.68,162.56 194.94,161.29 206.38,161.29 207.65,162.56 BAC0.JJ
BAC7
  Bottom 0.254: BAC1.NN 193.68,157.48 194.94,156.21 206.38,156.21 207.65,157.48 BAC0.NN
BAC8
  Bottom 0.254: BAC1.TT 193.68,152.4 194.94,151.13 206.38,151.13 207.65,152.4 BAC0.TT
BAC9
  Bottom 0.254: BAC1.D 193.68,195.58 194.94,196.85 206.38,196.85 207.65,195.58 BAC0.D
BAC10
  Bottom 0.254: BAC1.J 193.68,190.5 194.94,189.23 206.38,189.23 207.65,190.5 BAC0.J
BAC11
  Bottom 0.254: BAC1.N 193.68,185.42 194.94,184.15 206.38,184.15 207.65,185.42 BAC0.N
BMB0\
  Bottom 0.254: BMB1.F 163.19,193.04 164.47,194.31 175.9,194.31 177.16,193.04 BMB0.F
BMB1\
  Bottom 0.254: BMB1.L 163.19,187.96 164.47,186.69 175.9,186.69 177.16,187.96 BMB0.L
BMB2\
  Bottom 0.254: BMB1.R 163.19,182.88 164.47,181.61 175.9,181.61 177.16,182.88 BMB0.R
BMB3
  Bottom 0.254: BMB1.V 163.19,177.8 164.47,176.53 175.9,176.53 177.16,177.8 BMB0.V
BMB3\
  Bottom 0.254: BMB1.Z 163.19,172.72 164.47,171.45 175.9,171.45 177.16,172.72 BMB0.Z
BMB4
  Bottom 0.254: BMB1.DD 163.19,167.64 164.47,166.37 175.9,166.37 177.16,167.64 BMB0.DD
BMB4\
  Bottom 0.254: BMB1.JJ 163.19,162.56 164.47,161.29 175.9,161.29 177.16,162.56 BMB0.JJ
BMB5
  Bottom 0.254: BMB1.NN 163.19,157.48 164.47,156.21 175.9,156.21 177.16,157.48 BMB0.NN
BMB5\
  Bottom 0.254: BMB1.TT 163.19,152.4 164.47,151.13 175.9,151.13 177.16,152.4 BMB0.TT
BMB6
  Bottom 0.254: BMB1.D 163.19,195.58 164.47,196.85 175.9,196.85 177.16,195.58 BMB0.D
BMB6\
  Bottom 0.254: BMB1.J 163.19,190.5 164.47,189.23 175.9,189.23 177.16,190.5 BMB0.J
BMB7
  Bottom 0.254: BMB1.N 163.19,185.42 164.47,184.15 175.9,184.15 177.16,185.42 BMB0.N
BMB7\
  Bottom 0.254: BMB1.T 163.19,180.34 164.47,179.07 175.9,179.07 177.16,180.34 BMB0.T
BMB8
  Bottom 0.254: BMB1.X 163.19,175.26 164.47,173.99 175.9,173.99 177.16,175.26 BMB0.X
BMB8\
  Bottom 0.254: BMB1.BB 163.19,170.18 164.47,168.91 175.9,168.91 177.16,170.18 BMB0.BB
BMB9\
  Bottom 0.254: BMB1.FF 163.19,165.1 164.47,163.83 175.9,163.83 177.16,165.1 BMB0.FF
BMB10\
  Bottom 0.254: BMB1.LL 163.19,160.02 164.47,158.75 175.9,158.75 177.16,160.02 BMB0.LL
BMB11\
  Bottom 0.254: BMB1.RR 163.19,154.94 164.47,153.67 175.9,153.67 177.16,154.94 BMB0.RR
BREAK0\  (via drill 0.61)
  Top 0.254: v26.67,7.62 26.67,21.59 29.21,24.13 29.21,48.26 27.94,49.53 IC4.2 | v107.95,3.81 110.49,6.35 v110.49,12.7 | v156.21,11.43 156.84,12.06 v156.84,33.02
  Bottom 0.254: v26.67,7.62 30.48,3.81 v107.95,3.81 | v110.49,12.7 123.83,12.7 125.09,11.43 v156.21,11.43 | RN14.3 161.29,33.02 v156.84,33.02 152.4,37.47 ADDRESS0.BB
BREAK1\  (via drill 0.61)
  Top 0.254: v113.67,15.24 115.57,17.14 115.57,36.2 | 115.57,36.2 116.84,37.47 ADDRESS1.BB | 115.57,36.2 115.57,41.91 117.47,41.91 118.11,41.27 118.11,40.64 125.73,33.02 RN16.3
  Bottom 0.254: v113.67,15.24 111.76,15.24 107.31,10.79 19.05,10.79 19.05,21.59 18.41,22.23 10.79,22.23 10.79,45.09 15.24,49.53 IC4.7
BREAK2\  (via drill 0.61)
  Top 0.254: v80.01,41.91 80.01,40.01 81.28,38.73 ADDRESS2.BB | v85.72,38.1 85.72,37.47 90.17,33.02 RN18.3
  Bottom 0.254: v80.01,41.91 42.55,41.91 38.73,45.72 15.24,45.72 13.34,43.81 IC4.9 | v85.72,38.1 81.92,38.1 ADDRESS2.BB
BREAK3\
  Top 0.254: RN20.3 54.61,33.02 49.53,38.1 46.35,38.1 ADDRESS3.BB
  Bottom 0.254: IC4.15 27.94,41.91 31.75,38.1 41.27,38.1 42.55,36.83 43.81,36.83 45.09,38.1 ADDRESS3.BB
BREAK\  (via drill 0.61)
  Top 0.254: IC2.8 12.7,59.69 17.78,64.77 IC2.5 | v196.85,41.91 194.31,44.45 194.31,46.99 190.5,50.8 179.71,50.8 v179.71,66.67
  Bottom 0.254: 21.59,60.96 25.4,64.77 IC2.2 26.04,66.67 27.3,67.94 28.57,67.94 29.21,67.31 179.07,67.31 v179.71,66.67 | 21.59,60.96 20.32,59.69 IC2.11 | v196.85,41.91 202.56,41.91 205.1,39.37 216.53,39.37 217.81,38.1 ADDRESS.BB | 21.59,60.96 17.78,64.77 IC2.5
BRK_REQ  (via drill 0.61)
  Top 0.254: v39.37,127 41.27,128.91 v41.27,180.97
  Bottom 0.254: v39.37,127 34.29,127 IC19.11 | v41.27,180.97 43.81,183.51 64.14,183.51 65.41,184.78 IC31.15
BRK_REQ0\
  Top 0.254: 154.94,58.42 154.94,199.39 128.91,199.39 128.27,198.75 128.27,191.77 113.67,191.77 110.49,194.94 110.49,198.75 66.67,198.75 61.59,193.68 IC31.4 | 154.94,58.42 161.93,51.44 RN13.8 | 154.94,58.42 154.94,41.91 151.76,41.91 151.13,42.55 151.13,46.35 152.4,47.62 ADDRESS0.T
BRK_REQ1\
  Top 0.254: 118.11,52.07 118.11,50.16 116.84,48.9 ADDRESS1.T | 118.11,52.07 118.11,54.61 116.2,54.61 115.57,55.24 115.57,66.67 110.49,71.75 110.49,78.74 111.12,79.38 111.12,121.92 109.86,123.19 109.86,146.69 102.87,153.67 102.87,198.12 67.31,198.12 63.5,194.31 IC31.3 | 118.11,52.07 124.46,52.07 125.73,50.8 RN15.8
BRK_REQ2\  (via drill 0.61)
  Top 0.254: v69.85,144.78 69.85,173.99 67.94,173.99 67.31,174.62 67.31,176.53 65.41,176.53 64.77,175.9 64.77,173.99 62.87,173.99 62.23,174.62 62.23,186.69 65.41,189.87 65.41,191.13 66.04,191.77 IC31.2 | v74.3,142.24 76.2,140.34 76.2,71.12 77.47,69.85 v77.47,44.45 | v80.01,44.45 80.01,46.35 81.28,47.62 ADDRESS2.T | v84.45,48.26 v87,50.8
  Bottom 0.254: v69.85,144.78 72.39,142.24 v74.3,142.24 | v77.47,44.45 v80.01,44.45 | v87,50.8 90.17,50.8 RN17.8 | v84.45,48.26 81.92,48.26 ADDRESS2.T
BRK_REQ3\  (via drill 0.61)
  Top 0.254: v64.77,178.44 64.77,187.96 68.58,191.77 IC31.1 | v42.55,177.8 41.91,177.16 v41.91,46.99
  Bottom 0.254: RN19.8 54.61,50.8 52.7,48.9 45.72,48.9 ADDRESS3.T 45.09,48.26 43.81,46.99 v41.91,46.99 | v64.77,178.44 64.14,177.8 v42.55,177.8
BRK_REQ4\
  Top 0.254: IC31.13 60.33,186.06 59.05,187.32 57.15,187.32 57.15,174.62 55.88,173.35 SV1.9
BRK_REQ5\  (via drill 0.61)
  Top 0.254: v59.69,171.45 59.69,182.88 58.42,184.15 IC31.12
  Bottom 0.254: v59.69,171.45 55.24,171.45 53.98,172.72 SV1.7
BRK_REQ6\
  Top 0.254: IC31.11 55.88,184.15 52.07,180.34 52.07,174.62 50.8,173.35 SV1.5
BRK_REQ7\
  Top 0.254: IC31.10 53.34,184.15 49.53,180.34 49.53,174.62 48.26,173.35 SV1.3
BRK_REQ\  (via drill 0.61)
  Top 0.254: v35.56,147.96 35.56,124.46 33.66,122.56 IC19.9 | v104.14,149.22 108.58,144.78 v108.58,77.47
  Bottom 0.254: v35.56,147.96 36.83,149.22 v104.14,149.22 | v108.58,77.47 113.67,72.39 124.46,72.39 129.54,77.47 208.91,77.47 220.98,65.41 220.98,48.26 219.07,48.26 ADDRESS.T
BRK_SYNC_CLK
  Bottom 0.254: AC1.LL 132.72,160.02 133.99,158.75 145.41,158.75 146.69,160.02 AC0.LL
BTS1  (via drill 0.61)
  Top 0.254: v124.46,150.5 v109.86,165.1
  Bottom 0.254: v109.86,165.1 86.36,165.1 85.09,166.37 54.61,166.37 54.61,161.29 55.24,160.66 64.14,160.66 65.41,161.93 IC34.2 | v124.46,150.5 127.64,147.32 180.97,147.32 189.23,155.57 189.23,158.75 191.13,158.75 | 191.13,158.75 192.41,160.02 BAC1.LL | 191.13,158.75 206.38,158.75 207.65,160.02 BAC0.LL
BTS3
  Bottom 0.254: BAC1.FF 193.68,165.1 194.94,163.83 206.38,163.83 207.65,165.1 BAC0.FF
DA0  (via drill 0.61)
  Top 0.254: v73.03,60.96 76.2,64.14 v76.2,69.85 | v106.05,69.85 108.58,67.31 v108.58,60.96 | v118.11,59.69 125.09,66.67 v125.09,71.12 | v139.7,72.39 141.6,70.48 141.6,67.94 140.97,67.31 137.79,67.31 137.79,60.33 139.06,59.05 IC11.16
  Bottom 0.254: v73.03,60.96 72.39,60.96 69.85,58.42 IC7.16 | v106.05,69.85 v76.2,69.85 | IC9.16 105.41,58.42 106.05,58.42 v108.58,60.96 109.86,59.69 v118.11,59.69 | IC11.16 140.97,58.42 142.24,59.69 172.72,59.69 173.99,58.42 IC13.16 176.53,58.42 187.96,58.42 192.41,62.87 IC16.13 | v125.09,71.12 126.36,72.39 v139.7,72.39
DA0-0\  (via drill 0.61)
  Top 0.254: IC13.4 166.37,60.96 163.83,63.5 RN13.3 161.29,63.5 v158.75,60.96
  Bottom 0.254: v158.75,60.96 153.03,60.96 ADDRESS0.F
DA0-1\  (via drill 0.61)
  Top 0.254: v125.09,59.69 125.09,61.59 126.36,62.87 RN15.3
  Bottom 0.254: IC11.4 130.81,60.96 129.54,59.69 v125.09,59.69 119.38,59.69 118.11,60.96 117.47,60.96 ADDRESS1.F
DA0-2\
  Top 0.254: RN17.3 90.17,63.5 87.63,60.96 81.92,60.96 ADDRESS2.F
  Bottom 0.254: IC9.4 95.25,60.96 93.98,59.69 83.19,59.69 81.92,60.96 ADDRESS2.F
DA0-3\
  Bottom 0.254: 59.05,61.59 57.15,63.5 RN19.3 | 59.05,61.59 59.69,60.96 IC7.4 | 59.05,61.59 57.15,59.69 47.62,59.69 46.35,60.96 ADDRESS3.F
DA0\
  Bottom 0.254: IC16.15 198.75,62.87 201.93,59.69 216.53,59.69 217.81,60.96 ADDRESS.F
DA1  (via drill 0.61)
  Top 0.254: v187.96,52.07 187.96,62.23 IC16.11
  Bottom 0.254: 101.6,49.53 71.12,49.53 69.85,48.26 IC7.12 | 101.6,49.53 102.87,48.26 IC9.12 | 137.16,49.53 138.43,48.26 IC11.12 | 101.6,49.53 137.16,49.53 | 137.16,49.53 172.72,49.53 173.99,48.26 IC13.12 176.53,48.26 184.15,48.26 v187.96,52.07
DA1-0\  (via drill 0.61)
  Top 0.254: 160.66,55.88 160.66,56.52 161.93,57.78 RN13.5 | 160.66,55.88 160.66,54.61 163.83,54.61 167,51.44 IC13.8 | v160.02,55.88 160.66,55.88
  Bottom 0.254: v160.02,55.88 153.03,55.88 ADDRESS0.L
DA1-1\
  Top 0.254: 125.09,55.88 125.09,56.52 126.36,57.78 RN15.5 | 125.09,55.88 125.09,54.61 128.27,54.61 131.44,51.44 IC11.8 | 125.09,55.88 117.47,55.88 ADDRESS1.L
DA1-2\  (via drill 0.61)
  Top 0.254: v99.69,50.8 99.06,51.44 v99.06,58.42 | ADDRESS2.L 81.92,55.88 83.19,54.61 88.9,54.61 88.9,55.88 90.81,57.78 RN17.5
  Bottom 0.254: v99.69,50.8 97.79,50.8 IC9.8 | v99.06,58.42 97.79,59.69 95.25,59.69 93.98,58.42 92.71,58.42 RN17.5
DA1-3\  (via drill 0.61)
  Top 0.254: v62.87,57.15 62.87,52.7 61.59,51.44 IC7.8
  Bottom 0.254: v62.87,57.15 58.42,57.15 57.15,58.42 RN19.5 54.61,58.42 48.9,58.42 46.35,55.88 ADDRESS3.L
DA1\  (via drill 0.61)
  Top 0.254: v185.42,56.52 185.42,59.69 182.88,62.23 IC16.9
  Bottom 0.254: v185.42,56.52 187.32,54.61 216.53,54.61 217.81,55.88 ADDRESS.L
DA2  (via drill 0.61)
  Top 0.254: v177.8,25.4 186.69,34.29 186.69,39.37 192.41,45.09 IC15.4
  Bottom 0.254: 93.98,24.13 63.5,24.13 62.23,25.4 IC6.5 | 93.98,24.13 95.25,25.4 IC8.5 | 129.54,24.13 130.81,25.4 IC10.5 | 93.98,24.13 129.54,24.13 | 165.1,24.13 166.37,25.4 IC12.5 | 129.54,24.13 165.1,24.13 | v177.8,25.4 176.53,24.13 165.1,24.13
DA2-0\  (via drill 0.61)
  Top 0.254: v156.21,50.8 156.21,36.83 168.91,36.83 169.54,36.2 169.54,28.57 174.62,23.5 IC12.15 | v159.38,50.8 159.38,49.53 163.83,49.53 164.47,50.16 164.47,51.44 163.19,52.7 RN13.7
  Bottom 0.254: ADDRESS0.R 153.03,50.8 v156.21,50.8 v159.38,50.8
DA2-1\  (via drill 0.61)
  Top 0.254: v137.16,36.2 137.16,25.4 139.06,23.5 IC10.15 | v132.08,39.37 128.91,42.55 128.91,49.53 | 128.91,49.53 128.91,51.44 127.64,52.7 RN15.7 | v124.46,50.8 125.73,49.53 128.91,49.53
  Bottom 0.254: v137.16,36.2 133.99,39.37 v132.08,39.37 | v124.46,50.8 117.47,50.8 ADDRESS1.R
DA2-2\  (via drill 0.61)
  Top 0.254: v99.69,22.86 100.33,22.23 100.33,17.78 99.06,16.51 84.45,16.51 84.45,46.99 81.28,50.16 ADDRESS2.R 81.92,50.8 v84.45,53.34
  Bottom 0.254: v99.69,22.86 102.87,22.86 IC8.15 | v84.45,53.34 90.17,53.34 RN17.7
DA2-3\  (via drill 0.61)
  Top 0.254: v64.77,49.53 64.77,26.67 67.94,23.5 IC6.15
  Bottom 0.254: v64.77,49.53 62.23,52.07 58.42,52.07 57.15,53.34 RN19.7 54.61,53.34 48.9,53.34 46.35,50.8 ADDRESS3.R
DA2\  (via drill 0.61)
  Top 0.254: v217.17,46.99 217.17,48.9 218.44,50.16 ADDRESS.R
  Bottom 0.254: v217.17,46.99 215.26,46.99 214.63,47.62 200.03,47.62 198.75,46.35 IC15.2
DA3
  Bottom 0.254: 101.6,31.75 71.12,31.75 69.85,30.48 IC6.18 | 101.6,31.75 102.87,30.48 IC8.18 | 101.6,31.75 137.16,31.75 138.43,30.48 IC10.18 140.97,30.48 142.24,31.75 172.72,31.75 173.99,30.48 IC12.18 175.9,31.11 177.16,31.11 177.16,33.66 176.53,34.29 173.35,34.29 173.35,36.2 173.99,36.83 174.62,36.83 177.8,40.01 186.06,40.01 187.32,38.73 IC15.11
DA3-0\  (via drill 0.61)
  Top 0.254: v159.38,45.72 159.38,46.35 161.29,48.26 RN13.9
  Bottom 0.254: IC12.2 167,33.66 163.83,36.83 158.12,36.83 153.03,41.91 151.76,41.91 151.13,42.55 151.13,45.72 151.76,45.72 ADDRESS0.V 153.03,45.72 v159.38,45.72
DA3-1\
  Top 0.254: RN15.9 125.73,48.26 118.11,48.26 118.11,47.62 116.84,46.35 ADDRESS1.V
  Bottom 0.254: IC10.2 133.35,33.02 133.99,32.38 137.79,32.38 138.43,31.75 140.97,31.75 141.6,32.38 141.6,34.29 135.89,34.29 133.35,36.83 130.81,36.83 125.73,41.91 116.2,41.91 115.57,42.55 115.57,45.72 116.2,45.72 ADDRESS1.V
DA3-2\  (via drill 0.61)
  Top 0.254: 89.53,43.18 89.53,46.35 90.81,47.62 RN17.9 | 89.53,43.18 89.53,37.47 90.17,36.83 92.71,36.83 95.89,33.66 IC8.2 | v83.19,43.18 81.28,45.09 ADDRESS2.V | v90.17,43.18 89.53,43.18
  Bottom 0.254: v83.19,43.18 v90.17,43.18
DA3-3\  (via drill 0.61)
  Top 0.254: v63.5,45.72 63.5,35.56 61.59,33.66 IC6.2
  Bottom 0.254: v63.5,45.72 62.23,46.99 58.42,46.99 57.15,48.26 RN19.9 54.61,48.26 48.9,48.26 46.35,45.72 ADDRESS3.V
DA3\
  Bottom 0.254: IC15.9 183.51,37.47 184.78,36.2 193.68,36.2 194.31,36.83 194.31,43.18 214,43.18 215.26,44.45 216.53,44.45 217.81,45.72 ADDRESS.V
DA4  (via drill 0.61)
  Top 0.254: v72.39,25.4 77.47,20.32 v77.47,15.24 | IC8.16 104.78,24.77 107.31,22.23 107.31,14.61 v107.95,13.97 119.38,13.97 v119.38,10.16 | v144.15,25.4 148.59,20.95 148.59,10.79 | 148.59,10.79 155.57,3.81 173.35,3.81 173.35,20.95 173.99,21.59 177.16,21.59 177.16,23.5 175.9,24.77 IC12.16 175.9,26.04 184.15,34.29 184.15,39.37 189.87,45.09 IC15.5 | v141.6,3.81 148.59,10.79
  Bottom 0.254: v72.39,25.4 69.85,25.4 IC6.16 | v77.47,15.24 78.74,13.97 v107.95,13.97 | v144.15,25.4 140.97,25.4 IC10.16 | v119.38,10.16 125.73,3.81 v141.6,3.81
DA4-0\
  Top 0.254: IC12.4 167,28.57 164.47,31.11 164.47,33.66 163.19,34.92 RN14.2
  Bottom 0.254: ADDRESS0.Z 153.03,40.64 158.12,35.56 161.29,35.56 RN14.2
DA4-1\
  Top 0.254: 128.91,31.75 128.91,33.66 127.64,34.92 RN16.2 | 128.91,31.75 128.91,31.11 131.44,28.57 IC10.4 | 128.91,31.75 125.09,31.75 116.84,40.01 ADDRESS1.Z
DA4-2\  (via drill 0.61)
  Top 0.254: IC8.4 95.89,28.57 93.34,31.11 93.34,33.66 92.08,34.92 RN18.2 | v83.19,36.83 83.19,38.1 81.28,40.01 ADDRESS2.Z
  Bottom 0.254: v83.19,36.83 87.63,36.83 88.9,35.56 90.17,35.56 RN18.2
DA4-3\
  Top 0.254: IC6.4 60.33,28.57 57.78,31.11 57.78,33.66 56.52,34.92 RN20.2 55.24,36.2 52.07,39.37 52.07,40.64 46.35,40.64 ADDRESS3.Z
DA4\  (via drill 0.61)
  Top 0.254: v219.71,49.53 219.71,42.55 218.44,41.27 ADDRESS.Z
  Bottom 0.254: v219.71,49.53 189.23,49.53 186.06,46.35 IC15.7
DA5
  Top 0.254: 182.25,10.79 181.61,11.43 181.61,13.97 175.9,19.68 IC12.14 | 182.25,10.79 192.41,10.79 192.41,12.06 IC14.13 | 106.68,3.17 69.85,3.17 66.04,6.99 66.04,17.78 67.94,19.68 IC6.14 | 106.68,3.17 106.68,17.78 104.78,19.68 IC8.14 | 132.72,1.91 132.08,1.27 106.68,1.27 106.68,3.17 | 132.72,1.91 141.6,10.79 141.6,18.41 140.34,19.68 IC10.14 | 182.25,10.79 173.35,1.91 132.72,1.91
DA5-0\  (via drill 0.61)
  Top 0.254: IC12.6 167,23.5 164.47,26.04 164.47,28.57 163.19,29.84 RN14.4 | v155.57,30.48 155.57,31.75 152.4,34.92 ADDRESS0.DD
  Bottom 0.254: v155.57,30.48 161.29,30.48 RN14.4
DA5-1\
  Top 0.254: IC10.6 131.44,23.5 128.91,26.04 128.91,28.57 127.64,29.84 RN16.4 125.73,30.48 125.09,30.48 120.02,35.56 117.47,35.56 ADDRESS1.DD
DA5-2\  (via drill 0.61)
  Top 0.254: IC8.6 95.89,23.5 93.34,26.04 93.34,28.57 92.08,29.84 RN18.4 90.81,31.11 v86.36,35.56
  Bottom 0.254: v86.36,35.56 81.92,35.56 ADDRESS2.DD
DA5-3\
  Top 0.254: IC6.6 60.33,23.5 57.78,26.04 57.78,28.57 56.52,29.84 RN20.4 54.61,30.48 51.44,30.48 46.35,35.56 ADDRESS3.DD
DA5\
  Bottom 0.254: IC14.15 198.75,13.34 201.93,16.51 219.07,16.51 219.71,17.14 219.71,34.92 218.44,34.92 ADDRESS.DD
DA6
  Bottom 0.254: 93.98,19.05 67.31,19.05 66.67,19.68 62.87,19.68 62.23,20.32 IC6.7 | 93.98,19.05 95.25,20.32 IC8.7 | 129.54,19.05 130.81,20.32 IC10.7 | 93.98,19.05 129.54,19.05 | 165.1,19.05 166.37,20.32 IC12.7 | 129.54,19.05 165.1,19.05 | 165.1,19.05 176.53,19.05 177.16,18.41 191.13,18.41 192.41,19.68 IC14.4
DA6-0\  (via drill 0.61)
  Top 0.254: v154.94,26.04 153.67,27.3 153.67,28.57 152.4,29.84 ADDRESS0.JJ | v170.18,17.78 168.91,19.05 165.1,19.05 165.1,22.86 163.19,24.77 RN14.6
  Bottom 0.254: v154.94,26.04 160.66,26.04 161.29,25.4 RN14.6 | v170.18,17.78 173.99,17.78 IC12.13
DA6-1\  (via drill 0.61)
  Top 0.254: v122.56,25.4 117.47,30.48 ADDRESS1.JJ | v125.09,16.51 125.09,23.5 126.36,24.77 RN16.6
  Bottom 0.254: v122.56,25.4 125.73,25.4 RN16.6 | v125.09,16.51 137.16,16.51 138.43,17.78 IC10.13
DA6-2\  (via drill 0.61)
  Top 0.254: v85.72,30.48 85.72,29.84 90.17,25.4 RN18.6 92.08,24.77 93.34,23.5 93.34,20.95 95.25,19.05 97.79,19.05 v99.06,17.78
  Bottom 0.254: v85.72,30.48 81.92,30.48 ADDRESS2.JJ | v99.06,17.78 102.87,17.78 IC8.13
DA6-3\  (via drill 0.61)
  Top 0.254: v59.05,19.05 57.78,20.32 57.78,23.5 56.52,24.77 RN20.6
  Bottom 0.254: RN20.6 54.61,25.4 53.98,26.04 46.99,26.04 46.35,26.67 45.09,26.67 44.45,27.3 44.45,30.48 45.09,30.48 ADDRESS3.JJ | v59.05,19.05 66.04,19.05 67.31,17.78 IC6.13
DA6\
  Top 0.254: IC14.2 198.12,19.05 201.93,15.24 201.93,13.34 202.56,12.7 217.17,12.7 217.17,28.57 218.44,29.84 ADDRESS.JJ
DA7  (via drill 0.61)
  Top 0.254: 106.05,10.16 106.05,13.34 104.78,14.61 IC8.12 | 106.05,10.16 106.05,3.81 70.48,3.81 66.67,7.62 66.67,13.34 67.94,14.61 IC6.12 | 106.05,10.16 100.97,10.16 100.97,29.84 102.87,31.75 112.39,31.75 v112.39,35.56 | v129.54,35.56 130.81,34.29 135.25,34.29 135.25,20.95 137.79,18.41 137.79,17.14 139.06,15.88 IC10.12
  Bottom 0.254: IC10.12 140.97,15.24 141.6,14.61 160.66,14.61 161.29,13.97 172.72,13.97 173.99,15.24 IC12.12 176.53,15.24 185.42,15.24 187.32,13.34 IC14.11 | v112.39,35.56 113.67,36.83 128.27,36.83 v129.54,35.56
DA7-0\  (via drill 0.61)
  Top 0.254: RN14.8 163.19,19.68 165.1,17.78 166.37,17.78 IC12.8 | v155.57,20.32 155.57,21.59 152.4,24.77 ADDRESS0.NN
  Bottom 0.254: v155.57,20.32 161.29,20.32 RN14.8
DA7-1\  (via drill 0.61)
  Top 0.254: RN16.8 128.27,20.32 130.81,17.78 IC10.8 | v122.56,20.32 117.47,25.4 ADDRESS1.NN
  Bottom 0.254: v122.56,20.32 125.73,20.32 RN16.8
DA7-2\  (via drill 0.61)
  Top 0.254: IC8.8 95.25,17.78 92.71,20.32 RN18.8 90.81,20.95 v86.36,25.4
  Bottom 0.254: v86.36,25.4 81.92,25.4 ADDRESS2.NN
DA7-3\
  Bottom 0.254: IC6.8 59.69,17.78 58.42,17.78 56.52,19.68 RN20.8 55.24,20.95 48.26,20.95 47.62,21.59 44.45,21.59 44.45,23.5 45.72,24.77 ADDRESS3.NN
DA7\
  Top 0.254: IC14.9 183.51,13.34 184.78,14.61 199.39,14.61 199.39,11.43 200.03,10.79 219.71,10.79 219.71,23.5 218.44,24.77 ADDRESS.NN
DA8  (via drill 0.61)
  Top 0.254: v187.96,16.51 190.5,19.05 IC14.5
  Bottom 0.254: 93.98,16.51 63.5,16.51 62.23,15.24 IC6.9 | 93.98,16.51 95.25,15.24 IC8.9 | 93.98,16.51 122.56,16.51 125.09,13.97 129.54,13.97 130.81,15.24 IC10.9 133.35,15.24 137.16,15.24 138.43,16.51 165.1,16.51 | 165.1,16.51 166.37,15.24 IC12.9 | 165.1,16.51 v187.96,16.51
DA8-0\  (via drill 0.61)
  Top 0.254: ADDRESS0.TT 152.4,19.68 154.94,17.14 154.94,10.16 156.21,10.16 161.29,15.24 RN14.10 163.19,14.61 163.19,12.7 v164.47,11.43
  Bottom 0.254: v164.47,11.43 172.72,11.43 173.99,12.7 IC12.11
DA8-1\
  Top 0.254: IC10.11 138.43,12.7 138.43,11.43 130.81,11.43 127.64,14.61 RN16.10 125.73,15.24 125.73,9.53 121.92,9.53 120.65,10.79 120.65,15.88 116.84,19.68 ADDRESS1.TT
DA8-2\  (via drill 0.61)
  Top 0.254: ADDRESS2.TT 81.28,19.68 80.01,18.41 80.01,8.26 83.19,8.26 90.17,15.24 RN18.10 92.08,14.61 92.08,13.97 97.79,13.97 v99.06,12.7
  Bottom 0.254: v99.06,12.7 102.87,12.7 IC8.11
DA8-3\
  Bottom 0.254: ADDRESS3.TT 46.35,20.32 49.53,20.32 54.61,15.24 RN20.10 57.15,15.24 58.42,13.97 66.04,13.97 67.31,12.7 IC6.11
DA8\
  Bottom 0.254: IC14.7 186.06,20.95 187.32,22.23 214.63,22.23 215.26,21.59 216.53,21.59 217.81,20.32 ADDRESS.TT
DA9
  Bottom 0.254: IC16.4 192.41,70.48 187.32,65.41 178.44,65.41 176.53,63.5 IC13.18 173.99,63.5 172.72,64.77 137.16,64.77 | 101.6,64.77 71.12,64.77 69.85,63.5 IC7.18 | 101.6,64.77 102.87,63.5 IC9.18 | 137.16,64.77 138.43,63.5 IC11.18 | 137.16,64.77 101.6,64.77
DA9-0\  (via drill 0.61)
  Top 0.254: IC13.2 166.37,66.04 163.83,66.04 RN13.2 161.29,66.04 v158.75,63.5
  Bottom 0.254: v158.75,63.5 153.03,63.5 ADDRESS0.D
DA9-1\
  Top 0.254: 128.91,66.04 130.81,66.04 IC11.2 | 128.91,66.04 128.27,66.04 RN15.2 | 128.91,66.04 128.91,74.93 127,74.93 126.36,74.3 126.36,73.66 116.84,64.14 ADDRESS1.D
DA9-2\
  Top 0.254: ADDRESS2.D 81.92,63.5 88.9,63.5 90.81,65.41 RN17.2
  Bottom 0.254: RN17.2 92.71,66.04 95.25,66.04 IC9.2
DA9-3\
  Bottom 0.254: IC7.2 59.69,66.04 57.15,66.04 RN19.2 54.61,66.04 48.9,66.04 46.35,63.5 ADDRESS3.D
DA9\
  Bottom 0.254: IC16.2 198.75,70.48 203.2,66.04 206.38,66.04 207.65,64.77 216.53,64.77 217.81,63.5 ADDRESS.D
DA10  (via drill 0.61)
  Top 0.254: v189.23,53.34 189.23,68.58 190.5,69.85 IC16.5
  Bottom 0.254: 101.6,54.61 71.12,54.61 69.85,53.34 IC7.14 | 101.6,54.61 102.87,53.34 IC9.14 | 137.16,54.61 138.43,53.34 IC11.14 | 137.16,54.61 101.6,54.61 | 137.16,54.61 172.72,54.61 173.99,53.34 IC13.14 176.53,53.34 v189.23,53.34
DA10-0\  (via drill 0.61)
  Top 0.254: IC13.6 167,56.52 163.19,60.33 RN13.4 161.29,60.96 v158.75,58.42
  Bottom 0.254: v158.75,58.42 153.03,58.42 ADDRESS0.J
DA10-1\
  Top 0.254: 128.91,59.05 131.44,56.52 IC11.6 | 128.91,59.05 127.64,60.33 RN15.4 | 128.91,59.05 128.91,64.77 125.73,64.77 123.83,62.87 123.83,58.42 117.47,58.42 ADDRESS1.J
DA10-2\  (via drill 0.61)
  Top 0.254: v98.42,44.45 98.42,53.98 97.16,55.24 IC9.6 | v93.34,44.45 93.34,59.05 92.08,60.33 RN17.4 90.81,60.33 89.53,59.05 89.53,58.42 81.92,58.42 ADDRESS2.J
  Bottom 0.254: v93.34,44.45 v98.42,44.45
DA10-3\
  Bottom 0.254: 44.45,59.05 44.45,61.59 45.09,62.23 53.34,62.23 54.61,60.96 RN19.4 | 44.45,59.05 45.72,59.05 ADDRESS3.J | 44.45,59.05 44.45,55.24 45.09,54.61 46.35,54.61 48.9,57.15 57.15,57.15 57.78,56.52 59.05,56.52 59.69,55.88 IC7.6
DA10\  (via drill 0.61)
  Top 0.254: v186.69,56.52 186.69,68.58 185.42,69.85 IC16.7
  Bottom 0.254: v186.69,56.52 187.32,57.15 216.53,57.15 217.81,58.42 ADDRESS.J
DA11  (via drill 0.61)
  Top 0.254: v191.77,33.66 191.77,35.56 193.04,36.83 IC15.13
  Bottom 0.254: 93.98,29.21 63.5,29.21 62.23,30.48 IC6.3 | 93.98,29.21 95.25,30.48 IC8.3 | 129.54,29.21 130.81,30.48 IC10.3 | 93.98,29.21 129.54,29.21 | 165.1,29.21 166.37,30.48 IC12.3 | 129.54,29.21 165.1,29.21 | v191.77,33.66 187.32,29.21 165.1,29.21
DA11-0\  (via drill 0.61)
  Top 0.254: 172.72,46.99 172.72,50.8 168.91,54.61 165.1,54.61 163.83,55.88 RN13.6 | 172.72,46.99 172.72,30.48 174.62,28.57 IC12.17 | v156.21,53.34 158.12,51.44 158.12,45.72 159.38,44.45 165.74,44.45 165.74,46.35 166.37,46.99 172.72,46.99
  Bottom 0.254: v156.21,53.34 153.03,53.34 ADDRESS0.N
DA11-1\
  Top 0.254: 135.89,36.83 135.89,40.64 134.62,41.91 134.62,53.34 133.35,54.61 129.54,54.61 128.27,55.88 RN15.6 | 135.89,36.83 135.89,21.59 140.97,21.59 141.6,22.23 141.6,26.04 140.34,27.3 IC10.17 | 135.89,36.83 125.73,36.83 125.09,37.47 125.09,44.45 116.2,44.45 115.57,45.09 115.57,51.44 116.84,52.7 ADDRESS1.N
DA11-2\  (via drill 0.61)
  Top 0.254: v83.19,55.88 81.92,57.15 80.01,57.15 80.01,55.24 81.28,53.98 ADDRESS2.N | v99.69,27.94 99.06,28.57 v99.06,36.83 | v88.9,36.83 88.9,53.34 90.81,55.24 RN17.6
  Bottom 0.254: v83.19,55.88 90.17,55.88 RN17.6 | v99.69,27.94 102.87,27.94 IC8.17 | v88.9,36.83 v99.06,36.83
DA11-3\  (via drill 0.61)
  Top 0.254: v66.04,54.61 66.04,30.48 67.94,28.57 IC6.17
  Bottom 0.254: v66.04,54.61 59.05,54.61 57.78,55.88 57.15,55.88 RN19.6 54.61,55.88 48.9,55.88 46.35,53.34 ADDRESS3.N
DA11\  (via drill 0.61)
  Top 0.254: v201.93,50.8 201.93,43.18 198.12,39.37 IC15.15
  Bottom 0.254: v201.93,50.8 203.2,52.07 216.53,52.07 217.81,53.34 ADDRESS.N
DAEX0  (via drill 0.61)
  Top 0.254: v50.16,77.47 52.07,75.56 v52.07,54.61
  Bottom 0.254: 93.98,52.07 63.5,52.07 62.23,53.34 IC7.7 59.69,53.34 59.05,53.34 57.78,54.61 v52.07,54.61 | 93.98,52.07 95.25,53.34 IC9.7 | v50.16,77.47 26.67,77.47 23.5,80.64 IC5.5 | 129.54,52.07 130.81,53.34 IC11.7 | 93.98,52.07 129.54,52.07 | 129.54,52.07 165.1,52.07 166.37,53.34 IC13.7
DAEX0-0\  (via drill 0.61)
  Top 0.254: v170.18,87 170.18,85.09 170.81,84.45 170.81,55.24 174.62,51.44 IC13.13 | v156.21,93.98 157.48,92.71 v157.48,88.9
  Bottom 0.254: v170.18,87 169.54,87.63 165.1,87.63 163.83,88.9 RN2.9 161.29,88.9 v157.48,88.9 | v156.21,93.98 153.03,93.98 DATA0.RR
DAEX0-1\  (via drill 0.61)
  Top 0.254: v135.25,88.9 135.25,83.19 137.16,81.28 137.16,53.34 139.06,51.44 IC11.13 | v120.02,88.9 120.02,90.17 116.84,93.34 DATA1.RR
  Bottom 0.254: v135.25,88.9 134.62,89.53 133.99,89.53 133.35,90.17 130.81,90.17 129.54,88.9 128.27,88.9 RN6.9 125.73,88.9 v120.02,88.9
DAEX0-2\  (via drill 0.61)
  Top 0.254: v100.97,88.9 100.97,81.92 100.33,81.28 100.33,70.48 101.6,69.22 101.6,53.34 103.5,51.44 IC9.13 | v84.45,93.98 85.09,93.34 v85.09,88.9
  Bottom 0.254: v100.97,88.9 99.69,90.17 94.61,90.17 93.34,88.9 92.71,88.9 RN8.9 90.17,88.9 v85.09,88.9 | v84.45,93.98 81.92,93.98 DATA2.RR
DAEX0-3\  (via drill 0.61)
  Top 0.254: v64.77,87 65.41,86.36 65.41,56.52 67.31,54.61 66.67,53.98 66.67,52.7 67.94,51.44 IC7.13
  Bottom 0.254: v64.77,87 64.14,87.63 58.42,87.63 57.15,88.9 RN10.9 54.61,88.9 51.44,88.9 46.35,93.98 DATA3.RR
DAEX0\  (via drill 0.61)
  Top 0.254: v26.67,76.2 29.21,76.2 v29.21,69.85 | v111.76,71.75 120.02,71.75 v120.02,73.66 | v209.55,78.11 219.71,88.27 219.71,92.08 218.44,93.34 DATA.RR
  Bottom 0.254: v26.67,76.2 22.86,76.2 18.41,80.64 IC5.7 | v29.21,69.85 29.84,70.48 57.78,70.48 61.59,74.3 92.71,74.3 94.61,72.39 111.12,72.39 v111.76,71.75 | v120.02,73.66 124.46,78.11 v209.55,78.11
DAEX1  (via drill 0.61)
  Top 0.254: v59.69,76.2 60.96,74.93 60.96,70.48 61.59,69.85 62.87,69.85 62.87,60.33 61.59,59.05 IC7.5
  Bottom 0.254: 93.98,57.15 67.31,57.15 66.04,58.42 62.23,58.42 IC7.5 | 93.98,57.15 95.25,58.42 IC9.5 | v59.69,76.2 27.94,76.2 26.04,74.3 IC5.13 | 129.54,57.15 130.81,58.42 IC11.5 | 93.98,57.15 129.54,57.15 | 129.54,57.15 165.1,57.15 166.37,58.42 IC13.5
DAEX1-0\  (via drill 0.61)
  Top 0.254: v160.66,87.63 160.66,92.08 161.93,93.34 RN2.7 | DATA0.LL 152.4,98.42 153.67,97.16 v153.67,87.63 v153.67,76.2
  Bottom 0.254: v153.67,87.63 v160.66,87.63 | v153.67,76.2 194.31,76.2 194.31,62.23 189.87,57.78 178.44,57.78 176.53,55.88 IC13.15
DAEX1-1\  (via drill 0.61)
  Top 0.254: v145.41,55.88 144.78,56.52 v144.78,93.98 | v120.02,93.98 120.02,95.25 116.84,98.42 DATA1.LL
  Bottom 0.254: v145.41,55.88 140.97,55.88 IC11.15 | v144.78,93.98 144.15,93.34 141.6,93.34 140.97,92.71 137.16,92.71 135.25,94.61 133.99,94.61 133.35,95.25 130.18,95.25 128.91,93.98 128.27,93.98 RN6.7 125.73,93.98 v120.02,93.98
DAEX1-2\  (via drill 0.61)
  Top 0.254: v100.33,93.98 100.33,92.71 105.41,92.71 106.05,92.08 106.05,83.19 101.6,78.74 101.6,70.48 102.23,69.85 102.23,57.78 103.5,56.52 IC9.15 | v88.27,93.98 87,92.71 87,81.28 83.19,81.28 80.01,84.45 80.01,97.16 81.28,98.42 DATA2.LL
  Bottom 0.254: v100.33,93.98 99.69,94.61 98.42,94.61 97.79,95.25 95.25,95.25 93.98,93.98 92.71,93.98 RN8.7 90.17,93.98 v88.27,93.98
DAEX1-3\  (via drill 0.61)
  Top 0.254: v64.77,91.44 66.04,90.17 66.04,58.42 67.94,56.52 IC7.15
  Bottom 0.254: v64.77,91.44 63.5,92.71 58.42,92.71 57.15,93.98 RN10.7 54.61,93.98 53.34,95.25 44.45,95.25 44.45,97.16 45.72,98.42 DATA3.LL
DAEX1\
  Top 0.254: IC5.15 30.48,74.93 31.75,76.2 31.75,87.63 29.21,90.17 29.21,148.59 34.29,153.67 34.29,186.69 38.1,190.5 48.9,190.5 48.9,194.94 55.88,201.93 217.17,201.93 217.17,142.88 220.98,139.06 220.98,102.23 218.44,99.69 DATA.LL
DAEX2  (via drill 0.61)
  Top 0.254: v54.61,78.74 57.15,76.2 57.15,69.85 57.78,69.22 v57.78,64.77
  Bottom 0.254: 93.98,62.23 63.5,62.23 62.23,63.5 IC7.3 59.69,63.5 59.05,63.5 v57.78,64.77 | 93.98,62.23 95.25,63.5 IC9.3 | v54.61,78.74 27.94,78.74 26.04,80.64 IC5.4 | 129.54,62.23 130.81,63.5 IC11.3 | 93.98,62.23 129.54,62.23 | 129.54,62.23 165.1,62.23 166.37,63.5 IC13.3
DAEX2-0\  (via drill 0.61)
  Top 0.254: v169.54,62.23 169.54,69.85 168.28,69.85 158.75,79.38 158.75,88.9 158.12,89.53 158.12,91.44 159.38,92.71 159.38,95.89 161.93,98.42 RN2.5 | v151.13,107.95 151.13,106.05 152.4,104.78 DATA0.FF | v156.21,107.95 158.75,105.41 v158.75,99.06
  Bottom 0.254: v169.54,62.23 170.81,60.96 173.99,60.96 IC13.17 | v151.13,107.95 v156.21,107.95 | v158.75,99.06 161.29,99.06 RN2.5
DAEX2-1\  (via drill 0.61)
  Top 0.254: v122.56,99.06 117.47,104.14 DATA1.FF | v135.89,60.96 134.62,62.23 134.62,86.36 133.35,87.63 130.18,87.63 130.18,97.16 130.81,97.79 134.62,97.79 v134.62,99.06
  Bottom 0.254: v122.56,99.06 125.73,99.06 RN6.5 128.27,99.06 128.91,99.06 130.18,100.33 133.35,100.33 v134.62,99.06 | v135.89,60.96 138.43,60.96 IC11.17
DAEX2-2\  (via drill 0.61)
  Top 0.254: v85.09,99.06 82.55,101.6 82.55,102.23 81.28,103.5 DATA2.FF | v100.33,60.96 99.69,61.59 99.69,81.92 100.33,82.55 100.33,88.27 99.06,89.53 v99.06,99.06
  Bottom 0.254: v85.09,99.06 90.17,99.06 RN8.5 92.71,99.06 93.34,99.06 94.61,100.33 97.79,100.33 v99.06,99.06 | v100.33,60.96 102.87,60.96 IC9.17
DAEX2-3\  (via drill 0.61)
  Top 0.254: v64.14,60.96 63.5,61.59 v63.5,97.79 | v44.45,100.33 44.45,102.23 45.72,103.5 DATA3.FF
  Bottom 0.254: v64.14,60.96 67.31,60.96 IC7.17 | v63.5,97.79 58.42,97.79 57.15,99.06 RN10.5 54.61,99.06 50.8,99.06 49.53,100.33 v44.45,100.33
DAEX2\  (via drill 0.61)
  Top 0.254: v22.23,143.51 22.23,105.41 26.67,105.41 27.3,104.78 27.3,85.72 30.48,82.55 IC5.2 | v184.78,146.69 201.93,146.69 201.93,130.81 214.63,118.11 214.63,88.27 215.26,87.63 217.17,87.63 217.17,102.23 218.44,103.5 DATA.FF
  Bottom 0.254: v22.23,143.51 24.77,146.05 106.05,146.05 113.67,153.67 120.02,153.67 127,146.69 v184.78,146.69
DATA_OUT  (via drill 0.61)
  Top 0.254: v100.33,123.83 v100.33,138.43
